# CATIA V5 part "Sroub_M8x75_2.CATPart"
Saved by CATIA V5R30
Part number: Sroub_M8x75_2
Definition: E 1200_8x75_1
Nomenclature: E 1200_8x75_1
Source: Unknown
Description: PART--DESC
Bounding box of the stored display mesh (mm): x 123 to 136, y -24.99 to -12.01, z 11.2 to 94.2
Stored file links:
  E:\Bakalarka\Model\Forma_v7\Sroub_M8x75_2.CATPart
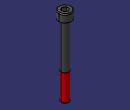
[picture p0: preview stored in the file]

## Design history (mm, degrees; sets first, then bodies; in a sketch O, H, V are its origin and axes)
Body1 "MANIFOLD_SOLID_BREP #3626" (main body)
  Solid1: solid without history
